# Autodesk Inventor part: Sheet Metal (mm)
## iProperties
Shininess: 64.0
Length Units: 11269
Angle Units: 11279
Time Units: 11290
Mass Units: 11283
Length Display Precision: 3
Angle Display Precision: 2
Compacted: True
Part Number: Sheet Metal (mm)
Document SubType Name: Sheet Metal
Created: 2002-07
Density: 0.0
Volumn: 0.0
Area: 0.0
PropertySet Name: Model Information
Control State: 0
Master: False
Checked Out: False
